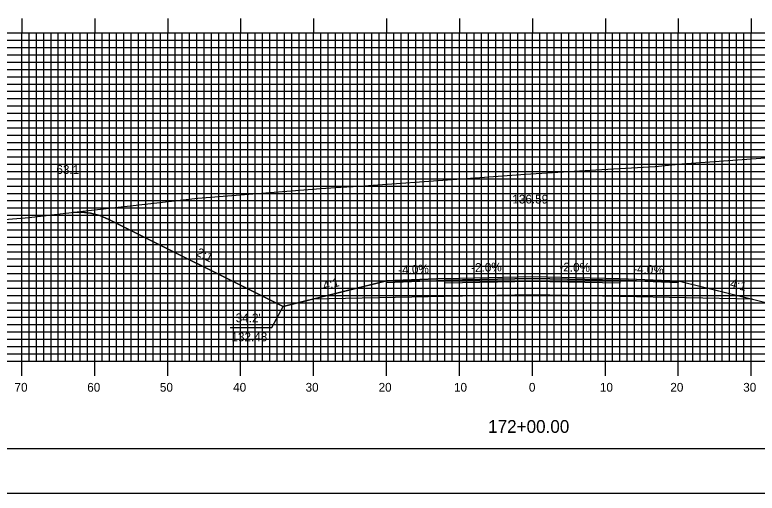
# Model space of a CAD drawing. Extents: x 1783041 to 1783384, y 442591 to 442811.
# Drawn here: x 1783135.5 to 1783237.3, y 442590.5 to 442656.2 of the extents above; entities that cross this region are included whole.
import ezdxf

# ---------------------------------------------------------------- set-up
doc = ezdxf.new("R2010")
doc.units = 0
for name, color, linetype in [('ANNOTATION', 7, 'Continuous'), ('BORDER', 7, 'Continuous'), ('D_Roadway_Centerline', 7, 'Continuous'), ('D_Roadway_Centerline_Text', 7, 'Continuous'), ('D_Roadway_Edge_Shoulder', 7, 'Continuous'), ('D_Roadway_Edge_TW', 7, 'Continuous'), ('D_Roadway_Pavement', 7, 'Continuous'), ('D_Roadway_SlopeLines', 7, 'Continuous'), ('D_Roadway_SubGrade', 7, 'Continuous'), ('D_Text_Standard', 7, 'Continuous'), ('H_V ANNOTATION', 7, 'Continuous'), ('MAJOR', 7, 'Continuous'), ('MINOR', 7, 'Continuous'), ('PLOT BOUNDARY', 7, 'Continuous'), ('S_Roadway_Centerline', 7, 'Continuous')]:
    doc.layers.add(name, color=color, linetype=linetype)

msp = doc.modelspace()

# ---------------------------------------------------------------- linework, layer by layer
at = {"layer": 'ANNOTATION'}
msp.add_lwpolyline([(1783165.04, 442613.26), (1783170.73, 442613.26), (1783172.29, 442616.15)], dxfattribs=at)
at = {"layer": 'BORDER'}
msp.add_lwpolyline([(1783056.86, 442596.67), (1783376.86, 442596.67), (1783376.86, 442806.67), (1783056.86, 442806.67)], close=True, dxfattribs=at)
at = {"layer": 'D_Roadway_Centerline'}
msp.add_lwpolyline([(1783143.39, 442629.05), (1783144.64, 442629.1), (1783145.89, 442628.96), (1783147.14, 442628.63), (1783148.39, 442628.1), (1783172.29, 442616.15), (1783176.29, 442617.15), (1783186.46, 442619.69), (1783194.46, 442620.01), (1783206.46, 442620.25), (1783218.46, 442620.01), (1783226.46, 442619.69), (1783236.63, 442617.15), (1783241.45, 442615.95), (1783288.24, 442639.34), (1783289.49, 442639.9), (1783290.74, 442640.32), (1783291.99, 442640.61), (1783293.24, 442640.77)], dxfattribs=at)
at = {"layer": 'D_Roadway_Edge_Shoulder'}
for points in [[(1783194.46, 442620.01), (1783186.46, 442619.69), (1783186.46, 442619.44), (1783194.46, 442619.76)], [(1783218.46, 442620.01), (1783226.46, 442619.69), (1783226.46, 442619.44), (1783218.46, 442619.76)]]:
    msp.add_lwpolyline(points, close=True, dxfattribs=at)
at = {"layer": 'D_Roadway_Edge_TW'}
msp.add_lwpolyline([(1783194.46, 442619.76), (1783194.46, 442620.01), (1783206.46, 442620.25), (1783218.46, 442620.01), (1783218.46, 442619.76), (1783206.46, 442620)], close=True, dxfattribs=at)
at = {"layer": 'D_Roadway_Pavement'}
msp.add_lwpolyline([(1783194.46, 442619.35), (1783194.46, 442619.76), (1783206.46, 442620), (1783218.46, 442619.76), (1783218.46, 442619.35), (1783206.46, 442619.59)], close=True, dxfattribs=at)
at = {"layer": 'D_Roadway_SlopeLines'}
for points in [[(1783172.29, 442616.15), (1783148.39, 442628.1), (1783147.14, 442628.63), (1783145.89, 442628.96), (1783144.64, 442629.1), (1783143.39, 442629.05)], [(1783186.46, 442619.69), (1783172.29, 442616.15)], [(1783226.46, 442619.69), (1783241.45, 442615.95)]]:
    msp.add_lwpolyline(points, dxfattribs=at)
at = {"layer": 'D_Roadway_SubGrade'}
msp.add_lwpolyline([(1783194.46, 442617.51), (1783176.29, 442617.15), (1783186.46, 442619.69), (1783186.46, 442619.44), (1783194.46, 442619.76), (1783206.46, 442620), (1783218.46, 442619.76), (1783226.46, 442619.44), (1783226.46, 442619.69), (1783236.63, 442617.15), (1783218.46, 442617.51), (1783206.46, 442617.75)], close=True, dxfattribs=at)
at = {"layer": 'MAJOR'}
for p, q in [((1783136.46, 442655.67), (1783136.46, 442653.67)), ((1783146.46, 442655.67), (1783146.46, 442653.67)), ((1783156.46, 442655.67), (1783156.46, 442653.67)), ((1783166.46, 442655.67), (1783166.46, 442653.67)), ((1783176.46, 442655.67), (1783176.46, 442653.67)), ((1783186.46, 442655.67), (1783186.46, 442653.67)), ((1783196.46, 442655.67), (1783196.46, 442653.67)), ((1783206.46, 442655.67), (1783206.46, 442653.67)), ((1783216.46, 442655.67), (1783216.46, 442653.67)), ((1783226.46, 442655.67), (1783226.46, 442653.67)), ((1783236.46, 442655.67), (1783236.46, 442653.67)), ((1783066.46, 442653.67), (1783346.46, 442653.67)), ((1783066.46, 442653.67), (1783346.46, 442653.67)), ((1783136.46, 442608.67), (1783136.46, 442653.67)), ((1783146.46, 442608.67), (1783146.46, 442653.67)), ((1783156.46, 442608.67), (1783156.46, 442653.67)), ((1783166.46, 442608.67), (1783166.46, 442653.67)), ((1783176.46, 442608.67), (1783176.46, 442653.67)), ((1783186.46, 442608.67), (1783186.46, 442653.67)), ((1783196.46, 442608.67), (1783196.46, 442653.67)), ((1783206.46, 442608.67), (1783206.46, 442653.67)), ((1783216.46, 442608.67), (1783216.46, 442653.67)), ((1783226.46, 442608.67), (1783226.46, 442653.67)), ((1783236.46, 442608.67), (1783236.46, 442653.67)), ((1783066.46, 442648.67), (1783346.46, 442648.67)), ((1783066.46, 442643.67), (1783346.46, 442643.67)), ((1783066.46, 442638.67), (1783346.46, 442638.67)), ((1783066.46, 442633.67), (1783346.46, 442633.67)), ((1783066.46, 442628.67), (1783346.46, 442628.67)), ((1783066.46, 442623.67), (1783346.46, 442623.67)), ((1783066.46, 442618.67), (1783346.46, 442618.67)), ((1783066.46, 442613.67), (1783346.46, 442613.67)), ((1783066.46, 442608.67), (1783346.46, 442608.67)), ((1783066.46, 442608.67), (1783346.46, 442608.67)), ((1783136.46, 442606.66), (1783136.46, 442608.67)), ((1783146.46, 442606.66), (1783146.46, 442608.67)), ((1783156.46, 442606.66), (1783156.46, 442608.67)), ((1783166.46, 442606.66), (1783166.46, 442608.67)), ((1783176.46, 442606.66), (1783176.46, 442608.67)), ((1783186.46, 442606.66), (1783186.46, 442608.67)), ((1783196.46, 442606.66), (1783196.46, 442608.67)), ((1783206.46, 442606.66), (1783206.46, 442608.67)), ((1783216.46, 442606.66), (1783216.46, 442608.67)), ((1783226.46, 442606.66), (1783226.46, 442608.67)), ((1783236.46, 442606.66), (1783236.46, 442608.67))]:
    msp.add_line(p, q, dxfattribs=at)
at = {"layer": 'MINOR'}
for p, q in [((1783137.46, 442608.67), (1783137.46, 442653.67)), ((1783138.46, 442608.67), (1783138.46, 442653.67)), ((1783139.46, 442608.67), (1783139.46, 442653.67)), ((1783140.46, 442608.67), (1783140.46, 442653.67)), ((1783141.46, 442608.67), (1783141.46, 442653.67)), ((1783142.46, 442608.67), (1783142.46, 442653.67)), ((1783143.46, 442608.67), (1783143.46, 442653.67)), ((1783144.46, 442608.67), (1783144.46, 442653.67)), ((1783145.46, 442608.67), (1783145.46, 442653.67)), ((1783147.46, 442608.67), (1783147.46, 442653.67)), ((1783148.46, 442608.67), (1783148.46, 442653.67)), ((1783149.46, 442608.67), (1783149.46, 442653.67)), ((1783150.46, 442608.67), (1783150.46, 442653.67)), ((1783151.46, 442608.67), (1783151.46, 442653.67)), ((1783152.46, 442608.67), (1783152.46, 442653.67)), ((1783153.46, 442608.67), (1783153.46, 442653.67)), ((1783154.46, 442608.67), (1783154.46, 442653.67)), ((1783155.46, 442608.67), (1783155.46, 442653.67)), ((1783157.46, 442608.67), (1783157.46, 442653.67)), ((1783158.46, 442608.67), (1783158.46, 442653.67)), ((1783159.46, 442608.67), (1783159.46, 442653.67)), ((1783160.46, 442608.67), (1783160.46, 442653.67)), ((1783161.46, 442608.67), (1783161.46, 442653.67)), ((1783162.46, 442608.67), (1783162.46, 442653.67)), ((1783163.46, 442608.67), (1783163.46, 442653.67)), ((1783164.46, 442608.67), (1783164.46, 442653.67)), ((1783165.46, 442608.67), (1783165.46, 442653.67)), ((1783167.46, 442608.67), (1783167.46, 442653.67)), ((1783168.46, 442608.67), (1783168.46, 442653.67)), ((1783169.46, 442608.67), (1783169.46, 442653.67)), ((1783170.46, 442608.67), (1783170.46, 442653.67)), ((1783171.46, 442608.67), (1783171.46, 442653.67)), ((1783172.46, 442608.67), (1783172.46, 442653.67)), ((1783173.46, 442608.67), (1783173.46, 442653.67)), ((1783174.46, 442608.67), (1783174.46, 442653.67)), ((1783175.46, 442608.67), (1783175.46, 442653.67)), ((1783177.46, 442608.67), (1783177.46, 442653.67)), ((1783178.46, 442608.67), (1783178.46, 442653.67)), ((1783179.46, 442608.67), (1783179.46, 442653.67)), ((1783180.46, 442608.67), (1783180.46, 442653.67)), ((1783181.46, 442608.67), (1783181.46, 442653.67)), ((1783182.46, 442608.67), (1783182.46, 442653.67)), ((1783183.46, 442608.67), (1783183.46, 442653.67)), ((1783184.46, 442608.67), (1783184.46, 442653.67)), ((1783185.46, 442608.67), (1783185.46, 442653.67)), ((1783187.46, 442608.67), (1783187.46, 442653.67)), ((1783188.46, 442608.67), (1783188.46, 442653.67)), ((1783189.46, 442608.67), (1783189.46, 442653.67)), ((1783190.46, 442608.67), (1783190.46, 442653.67)), ((1783191.46, 442608.67), (1783191.46, 442653.67)), ((1783192.46, 442608.67), (1783192.46, 442653.67)), ((1783193.46, 442608.67), (1783193.46, 442653.67)), ((1783194.46, 442608.67), (1783194.46, 442653.67)), ((1783195.46, 442608.67), (1783195.46, 442653.67)), ((1783197.46, 442608.67), (1783197.46, 442653.67)), ((1783198.46, 442608.67), (1783198.46, 442653.67)), ((1783199.46, 442608.67), (1783199.46, 442653.67)), ((1783200.46, 442608.67), (1783200.46, 442653.67)), ((1783201.46, 442608.67), (1783201.46, 442653.67)), ((1783202.46, 442608.67), (1783202.46, 442653.67)), ((1783203.46, 442608.67), (1783203.46, 442653.67)), ((1783204.46, 442608.67), (1783204.46, 442653.67)), ((1783205.46, 442608.67), (1783205.46, 442653.67)), ((1783207.46, 442608.67), (1783207.46, 442653.67)), ((1783208.46, 442608.67), (1783208.46, 442653.67)), ((1783209.46, 442608.67), (1783209.46, 442653.67)), ((1783210.46, 442608.67), (1783210.46, 442653.67)), ((1783211.46, 442608.67), (1783211.46, 442653.67)), ((1783212.46, 442608.67), (1783212.46, 442653.67)), ((1783213.46, 442608.67), (1783213.46, 442653.67)), ((1783214.46, 442608.67), (1783214.46, 442653.67)), ((1783215.46, 442608.67), (1783215.46, 442653.67)), ((1783217.46, 442608.67), (1783217.46, 442653.67)), ((1783218.46, 442608.67), (1783218.46, 442653.67)), ((1783219.46, 442608.67), (1783219.46, 442653.67)), ((1783220.46, 442608.67), (1783220.46, 442653.67)), ((1783221.46, 442608.67), (1783221.46, 442653.67)), ((1783222.46, 442608.67), (1783222.46, 442653.67)), ((1783223.46, 442608.67), (1783223.46, 442653.67)), ((1783224.46, 442608.67), (1783224.46, 442653.67)), ((1783225.46, 442608.67), (1783225.46, 442653.67)), ((1783227.46, 442608.67), (1783227.46, 442653.67)), ((1783228.46, 442608.67), (1783228.46, 442653.67)), ((1783229.46, 442608.67), (1783229.46, 442653.67)), ((1783230.46, 442608.67), (1783230.46, 442653.67)), ((1783231.46, 442608.67), (1783231.46, 442653.67)), ((1783232.46, 442608.67), (1783232.46, 442653.67)), ((1783233.46, 442608.67), (1783233.46, 442653.67)), ((1783234.46, 442608.67), (1783234.46, 442653.67)), ((1783235.46, 442608.67), (1783235.46, 442653.67)), ((1783066.46, 442652.67), (1783346.46, 442652.67)), ((1783066.46, 442651.67), (1783346.46, 442651.67)), ((1783066.46, 442650.67), (1783346.46, 442650.67)), ((1783066.46, 442649.67), (1783346.46, 442649.67)), ((1783066.46, 442647.67), (1783346.46, 442647.67)), ((1783066.46, 442646.67), (1783346.46, 442646.67)), ((1783066.46, 442645.67), (1783346.46, 442645.67)), ((1783066.46, 442644.67), (1783346.46, 442644.67)), ((1783066.46, 442642.67), (1783346.46, 442642.67)), ((1783066.46, 442641.67), (1783346.46, 442641.67)), ((1783066.46, 442640.67), (1783346.46, 442640.67)), ((1783066.46, 442639.67), (1783346.46, 442639.67)), ((1783066.46, 442637.67), (1783346.46, 442637.67)), ((1783066.46, 442636.67), (1783346.46, 442636.67)), ((1783066.46, 442635.67), (1783346.46, 442635.67)), ((1783066.46, 442634.67), (1783346.46, 442634.67)), ((1783066.46, 442632.67), (1783346.46, 442632.67)), ((1783066.46, 442631.67), (1783346.46, 442631.67)), ((1783066.46, 442630.67), (1783346.46, 442630.67)), ((1783066.46, 442629.67), (1783346.46, 442629.67)), ((1783066.46, 442627.67), (1783346.46, 442627.67)), ((1783066.46, 442626.67), (1783346.46, 442626.67)), ((1783066.46, 442625.67), (1783346.46, 442625.67)), ((1783066.46, 442624.67), (1783346.46, 442624.67)), ((1783066.46, 442622.67), (1783346.46, 442622.67)), ((1783066.46, 442621.67), (1783346.46, 442621.67)), ((1783066.46, 442620.67), (1783346.46, 442620.67)), ((1783066.46, 442619.67), (1783346.46, 442619.67)), ((1783066.46, 442617.67), (1783346.46, 442617.67)), ((1783066.46, 442616.67), (1783346.46, 442616.67)), ((1783066.46, 442615.67), (1783346.46, 442615.67)), ((1783066.46, 442614.67), (1783346.46, 442614.67)), ((1783066.46, 442612.67), (1783346.46, 442612.67)), ((1783066.46, 442611.67), (1783346.46, 442611.67)), ((1783066.46, 442610.67), (1783346.46, 442610.67)), ((1783066.46, 442609.67), (1783346.46, 442609.67))]:
    msp.add_line(p, q, dxfattribs=at)
at = {"layer": 'PLOT BOUNDARY'}
msp.add_lwpolyline([(1783040.67, 442590.55), (1783380.67, 442590.55), (1783380.67, 442810.55), (1783040.67, 442810.55)], close=True, dxfattribs=at)
at = {"layer": 'S_Roadway_Centerline'}
msp.add_lwpolyline([(1783066.46, 442623.05), (1783069.71, 442623.42), (1783076, 442624.18), (1783082.49, 442624.55), (1783087.28, 442624.78), (1783091.97, 442625.13), (1783110.35, 442626.8), (1783114.89, 442627.2), (1783133.49, 442628.06), (1783137.46, 442628.35), (1783145.58, 442629.31), (1783154.56, 442630.31), (1783160.6, 442631.03), (1783177.46, 442632.36), (1783180.18, 442632.54), (1783182.69, 442632.67), (1783196.75, 442633.66), (1783205.53, 442634.29), (1783215.14, 442634.91), (1783223.28, 442635.36), (1783226.96, 442635.7), (1783247.96, 442637.22)], dxfattribs=at)

# ---------------------------------------------------------------- texts
at = {"layer": 'ANNOTATION'}
for s, rotation, p in [('2:1', 333.4349, (1783160.27, 442623.19)), ('-4.0%', 2.2906, (1783188.09, 442620.56)), ('-2.0%', 1.1458, (1783198.07, 442620.89)), ('-2.0%', 358.8542, (1783210.15, 442620.98)), ('-4.0%', 357.7094, (1783220.25, 442620.74)), ('4:1', 14.0362, (1783177.91, 442618.42)), ('4:1', 345.9638, (1783233.46, 442618.8))]:
    msp.add_text(s, height=1.2, rotation=rotation, dxfattribs=at).set_placement(p)
for s, p in [("34.2'", (1783165.78, 442613.99)), ('132.48', (1783165.2, 442611.39))]:
    msp.add_text(s, height=1.2, dxfattribs=at).set_placement(p)
at = {"layer": 'D_Roadway_Centerline'}
for s, p in [('C', (1783206.45, 442620.25)), ('L', (1783206.46, 442620.25))]:
    msp.add_text(s, height=0.0146, dxfattribs=at).set_placement(p)
at = {"layer": 'D_Roadway_Centerline_Text'}
msp.add_text('136.59', height=1.2, dxfattribs=at).set_placement((1783203.71, 442630.28))
at = {"layer": 'D_Text_Standard'}
msp.add_text("63.1'", height=1.2, dxfattribs=at).set_placement((1783141.2, 442634.34))
at = {"layer": 'H_V ANNOTATION'}
for s, height, p in [('70', 1.2, (1783135.46, 442604.47)), ('60', 1.2, (1783145.43, 442604.47)), ('50', 1.2, (1783155.39, 442604.47)), ('40', 1.2, (1783165.43, 442604.47)), ('30', 1.2, (1783175.36, 442604.47)), ('20', 1.2, (1783185.37, 442604.47)), ('10', 1.2, (1783195.71, 442604.47)), ('0', 1.2, (1783205.98, 442604.47)), ('10', 1.2, (1783215.71, 442604.47)), ('20', 1.2, (1783225.37, 442604.47)), ('30', 1.2, (1783235.36, 442604.47)), ('172+00.00', 1.75, (1783200.39, 442598.82))]:
    msp.add_text(s, height=height, dxfattribs=at).set_placement(p)

doc.saveas('drawing.dxf')
